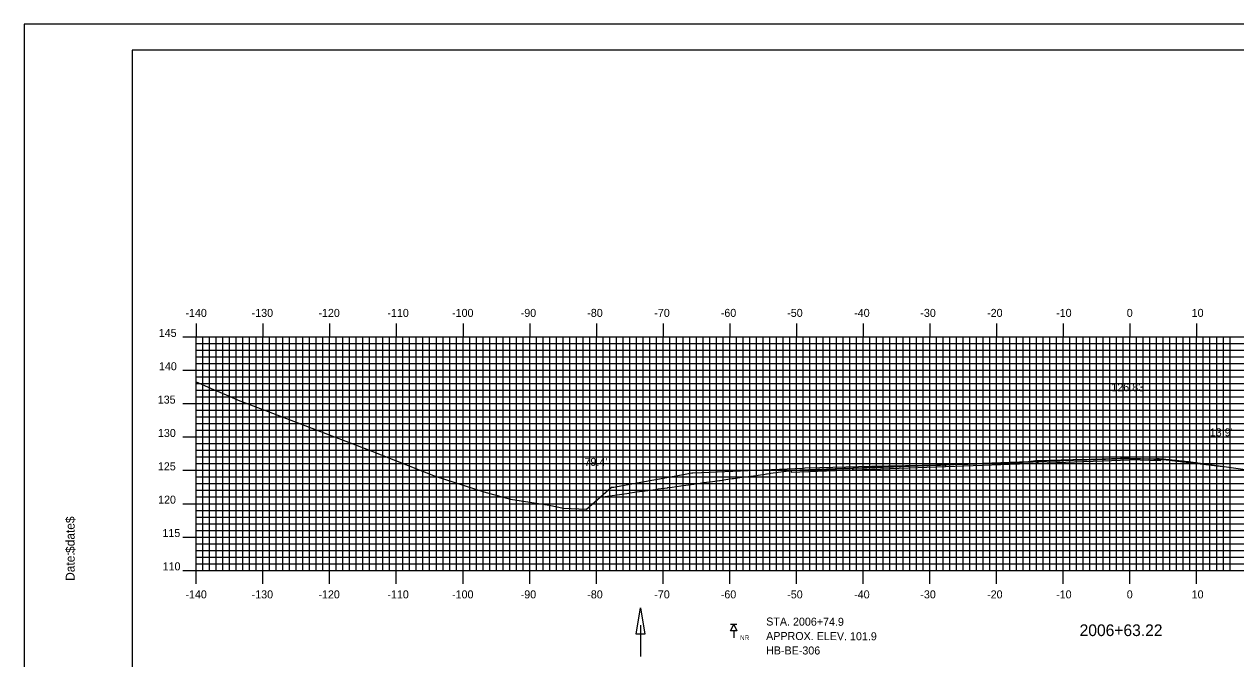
# Model space of a CAD drawing. Extents: x 852320 to 852663, y 366605 to 366825.
# Drawn here: x 852319.7 to 852501.3, y 366729.8 to 366824.9 of the extents above; entities that cross this region are included whole.
import ezdxf

# ---------------------------------------------------------------- set-up
doc = ezdxf.new("R2010")
doc.units = 0
for name, color, linetype in [('BORDER', 7, 'Continuous'), ('BORING - NO REFUSAL', 7, 'Continuous'), ('D_Drainage_Ditch_Line', 7, 'Continuous'), ('D_Roadway_Centerline', 7, 'Continuous'), ('D_Roadway_Centerline_Text', 7, 'Continuous'), ('D_Roadway_Edge_Shoulder', 7, 'Continuous'), ('D_Roadway_Edge_TW', 7, 'Continuous'), ('D_Roadway_SlopeLines', 7, 'Continuous'), ('D_Text_Standard', 7, 'Continuous'), ('H_V ANNOTATION', 7, 'Continuous'), ('MAJOR', 7, 'Continuous'), ('MINOR', 7, 'Continuous'), ('PLOT BOUNDARY', 7, 'Continuous'), ('S_Roadway_Centerline', 7, 'Continuous')]:
    doc.layers.add(name, color=color, linetype=linetype)

msp = doc.modelspace()

# ---------------------------------------------------------------- linework, layer by layer
at = {"layer": 'BORDER'}
msp.add_lwpolyline([(852335.88, 366611.06), (852655.88, 366611.06), (852655.88, 366821.06), (852335.88, 366821.06)], close=True, dxfattribs=at)
at = {"layer": 'BORING - NO REFUSAL'}
for p, q in [((852426.56, 366734.96), (852425.6, 366734.96)), ((852426.08, 366734), (852426.08, 366732.94))]:
    msp.add_line(p, q, dxfattribs=at)
msp.add_lwpolyline([(852426.08, 366734.96), (852426.56, 366734), (852425.6, 366734)], close=True, dxfattribs=at)
at = {"layer": 'D_Drainage_Ditch_Line'}
msp.add_line((852412.09, 366734.83), (852412.09, 366730.13), dxfattribs=at)
msp.add_lwpolyline([(852412.74, 366733.52), (852411.43, 366733.52), (852412.09, 366737.45)], close=True, dxfattribs=at)
at = {"layer": 'D_Roadway_Centerline'}
msp.add_lwpolyline([(852406.05, 366754.04), (852410.41, 366754.65), (852410.51, 366754.67), (852410.55, 366754.67), (852411.21, 366754.76), (852412.27, 366754.91), (852412.42, 366754.93), (852413.96, 366755.15), (852414.33, 366755.2), (852414.73, 366755.26), (852416.13, 366755.45), (852416.21, 366755.46), (852416.24, 366755.47), (852416.83, 366755.55), (852418.16, 366755.73), (852418.9, 366755.84), (852420.07, 366756), (852420.52, 366756.06), (852421.06, 366756.14), (852421.54, 366756.21), (852422, 366756.27), (852422.88, 366756.39), (852423.92, 366756.54), (852423.96, 366756.54), (852424.02, 366756.55), (852425.18, 366756.71), (852425.85, 366756.81), (852425.96, 366756.82), (852426.02, 366756.83), (852427.27, 366757.01), (852427.78, 366757.08), (852428.26, 366757.14), (852429.71, 366757.35), (852430.8, 366757.5), (852430.99, 366757.53), (852431.08, 366757.54), (852431.65, 366757.62), (852433.5, 366757.88), (852433.58, 366757.89), (852434.67, 366758.04), (852435.38, 366758.07), (852435.53, 366758.07), (852435.57, 366758.07), (852435.98, 366758.09), (852437.08, 366758.13), (852437.47, 366758.14), (852438.59, 366758.18), (852439.42, 366758.21), (852440.39, 366758.25), (852441, 366758.27), (852441.11, 366758.27), (852441.37, 366758.28), (852442.4, 366758.32), (852442.6, 366758.33), (852442.69, 366758.33), (852443.32, 366758.35), (852443.43, 366758.36), (852443.93, 366758.38), (852445.28, 366758.42), (852445.35, 366758.43), (852446.03, 366758.45), (852446.97, 366758.49), (852447.24, 366758.49), (852448.55, 366758.54), (852449.2, 366758.57), (852450.03, 366758.6), (852451.08, 366758.63), (852451.12, 366758.64), (852451.16, 366758.64), (852452.36, 366758.68), (852453.13, 366758.71), (852453.71, 366758.73), (852455.1, 366758.78), (852455.29, 366758.79), (852456.15, 366758.82), (852456.25, 366758.82), (852457.08, 366758.85), (852457.8, 366758.88), (852459.06, 366758.92), (852460.63, 366758.98), (852461.04, 366758.99), (852461.08, 366759), (852461.24, 366759), (852461.39, 366759.01), (852461.44, 366759.01), (852462.49, 366759.05), (852463.02, 366759.07), (852463.9, 366759.1), (852465.01, 366759.14), (852465.78, 366759.17), (852466.35, 366759.19), (852466.59, 366759.2), (852467, 366759.21), (852468.54, 366759.27), (852468.99, 366759.28), (852469.32, 366759.29), (852470.98, 366759.35), (852471.01, 366759.36), (852471.48, 366759.37), (852471.65, 366759.38), (852472.85, 366759.42), (852472.98, 366759.43), (852474.56, 366759.48), (852474.98, 366759.5), (852475.44, 366759.52), (852476.63, 366759.56), (852476.76, 366759.57), (852476.99, 366759.57), (852478.06, 366759.61), (852478.99, 366759.65), (852479.94, 366759.68), (852480.57, 366759.7), (852480.72, 366759.71), (852481.01, 366759.72), (852481.58, 366759.74), (852481.8, 366759.75), (852482.1, 366759.76), (852483.02, 366759.79), (852483.33, 366759.8), (852485.04, 366759.87), (852485.09, 366759.87), (852485.48, 366759.88), (852487, 366759.83), (852487.04, 366759.82), (852487.06, 366759.82), (852488.3, 366759.78), (852489.08, 366759.75), (852489.38, 366759.73), (852490.08, 366759.71)], dxfattribs=at)
at = {"layer": 'D_Roadway_Edge_Shoulder'}
for points in [[(852485.48, 366759.88), (852490.08, 366759.71), (852490.08, 366759.46), (852485.48, 366759.63)], [(852443.93, 366758.38), (852434.67, 366758.04), (852434.67, 366757.79), (852443.93, 366758.13)]]:
    msp.add_lwpolyline(points, close=True, dxfattribs=at)
at = {"layer": 'D_Roadway_Edge_TW'}
for points in [[(852471.65, 366759.38), (852457.8, 366758.88), (852457.8, 366758.63), (852471.65, 366759.13)], [(852485.48, 366759.88), (852471.65, 366759.38), (852471.65, 366759.13), (852485.48, 366759.63)], [(852457.8, 366758.88), (852443.93, 366758.38), (852443.93, 366758.13), (852457.8, 366758.63)]]:
    msp.add_lwpolyline(points, close=True, dxfattribs=at)
msp.add_lwpolyline([(852457.8, 366758.63), (852457.8, 366758.88)], dxfattribs=at)
at = {"layer": 'D_Roadway_SlopeLines'}
msp.add_line((852490.08, 366759.71), (852499.39, 366758.65), dxfattribs=at)
at = {"layer": 'MAJOR'}
for p, q in [((852345.48, 366780.06), (852345.48, 366778.06)), ((852355.48, 366780.06), (852355.48, 366778.06)), ((852365.48, 366780.06), (852365.48, 366778.06)), ((852375.48, 366780.06), (852375.48, 366778.06)), ((852385.48, 366780.06), (852385.48, 366778.06)), ((852395.48, 366780.06), (852395.48, 366778.06)), ((852405.48, 366780.06), (852405.48, 366778.06)), ((852415.48, 366780.06), (852415.48, 366778.06)), ((852425.48, 366780.06), (852425.48, 366778.06)), ((852435.48, 366780.06), (852435.48, 366778.06)), ((852445.48, 366780.06), (852445.48, 366778.06)), ((852455.48, 366780.06), (852455.48, 366778.06)), ((852465.48, 366780.06), (852465.48, 366778.06)), ((852475.48, 366780.06), (852475.48, 366778.06)), ((852485.48, 366780.06), (852485.48, 366778.06)), ((852495.48, 366780.06), (852495.48, 366778.06)), ((852343.47, 366778.06), (852345.48, 366778.06)), ((852345.48, 366778.06), (852625.48, 366778.06)), ((852345.48, 366743.06), (852345.48, 366778.06)), ((852345.48, 366743.06), (852345.48, 366778.06)), ((852345.48, 366778.06), (852625.48, 366778.06)), ((852355.48, 366743.06), (852355.48, 366778.06)), ((852365.48, 366743.06), (852365.48, 366778.06)), ((852375.48, 366743.06), (852375.48, 366778.06)), ((852385.48, 366743.06), (852385.48, 366778.06)), ((852395.48, 366743.06), (852395.48, 366778.06)), ((852405.48, 366743.06), (852405.48, 366778.06)), ((852415.48, 366743.06), (852415.48, 366778.06)), ((852425.48, 366743.06), (852425.48, 366778.06)), ((852435.48, 366743.06), (852435.48, 366778.06)), ((852445.48, 366743.06), (852445.48, 366778.06)), ((852455.48, 366743.06), (852455.48, 366778.06)), ((852465.48, 366743.06), (852465.48, 366778.06)), ((852475.48, 366743.06), (852475.48, 366778.06)), ((852485.48, 366743.06), (852485.48, 366778.06)), ((852495.48, 366743.06), (852495.48, 366778.06)), ((852343.47, 366773.06), (852345.48, 366773.06)), ((852345.48, 366773.06), (852625.48, 366773.06)), ((852343.47, 366768.06), (852345.48, 366768.06)), ((852345.48, 366768.06), (852625.48, 366768.06)), ((852343.47, 366763.06), (852345.48, 366763.06)), ((852345.48, 366763.06), (852625.48, 366763.06)), ((852343.47, 366758.06), (852345.48, 366758.06)), ((852345.48, 366758.06), (852625.48, 366758.06)), ((852343.47, 366753.06), (852345.48, 366753.06)), ((852345.48, 366753.06), (852625.48, 366753.06)), ((852343.47, 366748.06), (852345.48, 366748.06)), ((852345.48, 366748.06), (852625.48, 366748.06)), ((852343.47, 366743.06), (852345.48, 366743.06)), ((852345.48, 366743.06), (852625.48, 366743.06)), ((852345.48, 366743.06), (852625.48, 366743.06)), ((852345.48, 366741.05), (852345.48, 366743.06)), ((852355.48, 366741.05), (852355.48, 366743.06)), ((852365.48, 366741.05), (852365.48, 366743.06)), ((852375.48, 366741.05), (852375.48, 366743.06)), ((852385.48, 366741.05), (852385.48, 366743.06)), ((852395.48, 366741.05), (852395.48, 366743.06)), ((852405.48, 366741.05), (852405.48, 366743.06)), ((852415.48, 366741.05), (852415.48, 366743.06)), ((852425.48, 366741.05), (852425.48, 366743.06)), ((852435.48, 366741.05), (852435.48, 366743.06)), ((852445.48, 366741.05), (852445.48, 366743.06)), ((852455.48, 366741.05), (852455.48, 366743.06)), ((852465.48, 366741.05), (852465.48, 366743.06)), ((852475.48, 366741.05), (852475.48, 366743.06)), ((852485.48, 366741.05), (852485.48, 366743.06)), ((852495.48, 366741.05), (852495.48, 366743.06))]:
    msp.add_line(p, q, dxfattribs=at)
at = {"layer": 'MINOR'}
for p, q in [((852345.48, 366743.06), (852345.48, 366778.06)), ((852345.48, 366777.06), (852625.48, 366777.06)), ((852345.48, 366777.06), (852347.48, 366777.06)), ((852346.48, 366743.06), (852346.48, 366778.06)), ((852347.48, 366743.06), (852347.48, 366778.06)), ((852348.48, 366743.06), (852348.48, 366778.06)), ((852349.48, 366743.06), (852349.48, 366778.06)), ((852350.48, 366743.06), (852350.48, 366778.06)), ((852351.48, 366743.06), (852351.48, 366778.06)), ((852352.48, 366743.06), (852352.48, 366778.06)), ((852353.48, 366743.06), (852353.48, 366778.06)), ((852354.48, 366743.06), (852354.48, 366778.06)), ((852356.48, 366743.06), (852356.48, 366778.06)), ((852357.48, 366743.06), (852357.48, 366778.06)), ((852358.48, 366743.06), (852358.48, 366778.06)), ((852359.48, 366743.06), (852359.48, 366778.06)), ((852360.48, 366743.06), (852360.48, 366778.06)), ((852361.48, 366743.06), (852361.48, 366778.06)), ((852362.48, 366743.06), (852362.48, 366778.06)), ((852363.48, 366743.06), (852363.48, 366778.06)), ((852364.48, 366743.06), (852364.48, 366778.06)), ((852366.48, 366743.06), (852366.48, 366778.06)), ((852367.48, 366743.06), (852367.48, 366778.06)), ((852368.48, 366743.06), (852368.48, 366778.06)), ((852369.48, 366743.06), (852369.48, 366778.06)), ((852370.48, 366743.06), (852370.48, 366778.06)), ((852371.48, 366743.06), (852371.48, 366778.06)), ((852372.48, 366743.06), (852372.48, 366778.06)), ((852373.48, 366743.06), (852373.48, 366778.06)), ((852374.48, 366743.06), (852374.48, 366778.06)), ((852376.48, 366743.06), (852376.48, 366778.06)), ((852377.48, 366743.06), (852377.48, 366778.06)), ((852378.48, 366743.06), (852378.48, 366778.06)), ((852379.48, 366743.06), (852379.48, 366778.06)), ((852380.48, 366743.06), (852380.48, 366778.06)), ((852381.48, 366743.06), (852381.48, 366778.06)), ((852382.48, 366743.06), (852382.48, 366778.06)), ((852383.48, 366743.06), (852383.48, 366778.06)), ((852384.48, 366743.06), (852384.48, 366778.06)), ((852386.48, 366743.06), (852386.48, 366778.06)), ((852387.48, 366743.06), (852387.48, 366778.06)), ((852388.48, 366743.06), (852388.48, 366778.06)), ((852389.48, 366743.06), (852389.48, 366778.06)), ((852390.48, 366743.06), (852390.48, 366778.06)), ((852391.48, 366743.06), (852391.48, 366778.06)), ((852392.48, 366743.06), (852392.48, 366778.06)), ((852393.48, 366743.06), (852393.48, 366778.06)), ((852394.48, 366743.06), (852394.48, 366778.06)), ((852396.48, 366743.06), (852396.48, 366778.06)), ((852397.48, 366743.06), (852397.48, 366778.06)), ((852398.48, 366743.06), (852398.48, 366778.06)), ((852399.48, 366743.06), (852399.48, 366778.06)), ((852400.48, 366743.06), (852400.48, 366778.06)), ((852401.48, 366743.06), (852401.48, 366778.06)), ((852402.48, 366743.06), (852402.48, 366778.06)), ((852403.48, 366743.06), (852403.48, 366778.06)), ((852404.48, 366743.06), (852404.48, 366778.06)), ((852406.48, 366743.06), (852406.48, 366778.06)), ((852407.48, 366743.06), (852407.48, 366778.06)), ((852408.48, 366743.06), (852408.48, 366778.06)), ((852409.48, 366743.06), (852409.48, 366778.06)), ((852410.48, 366743.06), (852410.48, 366778.06)), ((852411.48, 366743.06), (852411.48, 366778.06)), ((852412.48, 366743.06), (852412.48, 366778.06)), ((852413.48, 366743.06), (852413.48, 366778.06)), ((852414.48, 366743.06), (852414.48, 366778.06)), ((852416.48, 366743.06), (852416.48, 366778.06)), ((852417.48, 366743.06), (852417.48, 366778.06)), ((852418.48, 366743.06), (852418.48, 366778.06)), ((852419.48, 366743.06), (852419.48, 366778.06)), ((852420.48, 366743.06), (852420.48, 366778.06)), ((852421.48, 366743.06), (852421.48, 366778.06)), ((852422.48, 366743.06), (852422.48, 366778.06)), ((852423.48, 366743.06), (852423.48, 366778.06)), ((852424.48, 366743.06), (852424.48, 366778.06)), ((852426.48, 366743.06), (852426.48, 366778.06)), ((852427.48, 366743.06), (852427.48, 366778.06)), ((852428.48, 366743.06), (852428.48, 366778.06)), ((852429.48, 366743.06), (852429.48, 366778.06)), ((852430.48, 366743.06), (852430.48, 366778.06)), ((852431.48, 366743.06), (852431.48, 366778.06)), ((852432.48, 366743.06), (852432.48, 366778.06)), ((852433.48, 366743.06), (852433.48, 366778.06)), ((852434.48, 366743.06), (852434.48, 366778.06)), ((852436.48, 366743.06), (852436.48, 366778.06)), ((852437.48, 366743.06), (852437.48, 366778.06)), ((852438.48, 366743.06), (852438.48, 366778.06)), ((852439.48, 366743.06), (852439.48, 366778.06)), ((852440.48, 366743.06), (852440.48, 366778.06)), ((852441.48, 366743.06), (852441.48, 366778.06)), ((852442.48, 366743.06), (852442.48, 366778.06)), ((852443.48, 366743.06), (852443.48, 366778.06)), ((852444.48, 366743.06), (852444.48, 366778.06)), ((852446.48, 366743.06), (852446.48, 366778.06)), ((852447.48, 366743.06), (852447.48, 366778.06)), ((852448.48, 366743.06), (852448.48, 366778.06)), ((852449.48, 366743.06), (852449.48, 366778.06)), ((852450.48, 366743.06), (852450.48, 366778.06)), ((852451.48, 366743.06), (852451.48, 366778.06)), ((852452.48, 366743.06), (852452.48, 366778.06)), ((852453.48, 366743.06), (852453.48, 366778.06)), ((852454.48, 366743.06), (852454.48, 366778.06)), ((852456.48, 366743.06), (852456.48, 366778.06)), ((852457.48, 366743.06), (852457.48, 366778.06)), ((852458.48, 366743.06), (852458.48, 366778.06)), ((852459.48, 366743.06), (852459.48, 366778.06)), ((852460.48, 366743.06), (852460.48, 366778.06)), ((852461.48, 366743.06), (852461.48, 366778.06)), ((852462.48, 366743.06), (852462.48, 366778.06)), ((852463.48, 366743.06), (852463.48, 366778.06)), ((852464.48, 366743.06), (852464.48, 366778.06)), ((852466.48, 366743.06), (852466.48, 366778.06)), ((852467.48, 366743.06), (852467.48, 366778.06)), ((852468.48, 366743.06), (852468.48, 366778.06)), ((852469.48, 366743.06), (852469.48, 366778.06)), ((852470.48, 366743.06), (852470.48, 366778.06)), ((852471.48, 366743.06), (852471.48, 366778.06)), ((852472.48, 366743.06), (852472.48, 366778.06)), ((852473.48, 366743.06), (852473.48, 366778.06)), ((852474.48, 366743.06), (852474.48, 366778.06)), ((852476.48, 366743.06), (852476.48, 366778.06)), ((852477.48, 366743.06), (852477.48, 366778.06)), ((852478.48, 366743.06), (852478.48, 366778.06)), ((852479.48, 366743.06), (852479.48, 366778.06)), ((852480.48, 366743.06), (852480.48, 366778.06)), ((852481.48, 366743.06), (852481.48, 366778.06)), ((852482.48, 366743.06), (852482.48, 366778.06)), ((852483.48, 366743.06), (852483.48, 366778.06)), ((852484.48, 366743.06), (852484.48, 366778.06)), ((852486.48, 366743.06), (852486.48, 366778.06)), ((852487.48, 366743.06), (852487.48, 366778.06)), ((852488.48, 366743.06), (852488.48, 366778.06)), ((852489.48, 366743.06), (852489.48, 366778.06)), ((852490.48, 366743.06), (852490.48, 366778.06)), ((852491.48, 366743.06), (852491.48, 366778.06)), ((852492.48, 366743.06), (852492.48, 366778.06)), ((852493.48, 366743.06), (852493.48, 366778.06)), ((852494.48, 366743.06), (852494.48, 366778.06)), ((852496.48, 366743.06), (852496.48, 366778.06)), ((852497.48, 366743.06), (852497.48, 366778.06)), ((852498.48, 366743.06), (852498.48, 366778.06)), ((852499.48, 366743.06), (852499.48, 366778.06)), ((852500.48, 366743.06), (852500.48, 366778.06)), ((852345.48, 366776.06), (852625.48, 366776.06)), ((852345.48, 366776.06), (852347.48, 366776.06)), ((852345.48, 366775.06), (852625.48, 366775.06)), ((852345.48, 366775.06), (852347.48, 366775.06)), ((852345.48, 366774.06), (852625.48, 366774.06)), ((852345.48, 366774.06), (852347.48, 366774.06)), ((852345.48, 366772.06), (852625.48, 366772.06)), ((852345.48, 366772.06), (852347.48, 366772.06)), ((852345.48, 366771.06), (852625.48, 366771.06)), ((852345.48, 366771.06), (852347.48, 366771.06)), ((852345.48, 366770.06), (852625.48, 366770.06)), ((852345.48, 366770.06), (852347.48, 366770.06)), ((852345.48, 366769.06), (852625.48, 366769.06)), ((852345.48, 366769.06), (852347.48, 366769.06)), ((852345.48, 366767.06), (852625.48, 366767.06)), ((852345.48, 366767.06), (852347.48, 366767.06)), ((852345.48, 366766.06), (852625.48, 366766.06)), ((852345.48, 366766.06), (852347.48, 366766.06)), ((852345.48, 366765.06), (852625.48, 366765.06)), ((852345.48, 366765.06), (852347.48, 366765.06)), ((852345.48, 366764.06), (852625.48, 366764.06)), ((852345.48, 366764.06), (852347.48, 366764.06)), ((852345.48, 366762.06), (852625.48, 366762.06)), ((852345.48, 366762.06), (852347.48, 366762.06)), ((852345.48, 366761.06), (852625.48, 366761.06)), ((852345.48, 366761.06), (852347.48, 366761.06)), ((852345.48, 366760.06), (852625.48, 366760.06)), ((852345.48, 366760.06), (852347.48, 366760.06)), ((852345.48, 366759.06), (852625.48, 366759.06)), ((852345.48, 366759.06), (852347.48, 366759.06)), ((852345.48, 366757.06), (852625.48, 366757.06)), ((852345.48, 366757.06), (852347.48, 366757.06)), ((852345.48, 366756.06), (852625.48, 366756.06)), ((852345.48, 366756.06), (852347.48, 366756.06)), ((852345.48, 366755.06), (852625.48, 366755.06)), ((852345.48, 366755.06), (852347.48, 366755.06)), ((852345.48, 366754.06), (852625.48, 366754.06)), ((852345.48, 366754.06), (852347.48, 366754.06)), ((852345.48, 366752.06), (852625.48, 366752.06)), ((852345.48, 366752.06), (852347.48, 366752.06)), ((852345.48, 366751.06), (852625.48, 366751.06)), ((852345.48, 366751.06), (852347.48, 366751.06)), ((852345.48, 366750.06), (852625.48, 366750.06)), ((852345.48, 366750.06), (852347.48, 366750.06)), ((852345.48, 366749.06), (852625.48, 366749.06)), ((852345.48, 366749.06), (852347.48, 366749.06)), ((852345.48, 366747.06), (852625.48, 366747.06)), ((852345.48, 366747.06), (852347.48, 366747.06)), ((852345.48, 366746.06), (852625.48, 366746.06)), ((852345.48, 366746.06), (852347.48, 366746.06)), ((852345.48, 366745.06), (852625.48, 366745.06)), ((852345.48, 366745.06), (852347.48, 366745.06)), ((852345.48, 366744.06), (852625.48, 366744.06)), ((852345.48, 366744.06), (852347.48, 366744.06))]:
    msp.add_line(p, q, dxfattribs=at)
at = {"layer": 'PLOT BOUNDARY'}
msp.add_lwpolyline([(852319.69, 366604.94), (852659.69, 366604.94), (852659.69, 366824.94), (852319.69, 366824.94)], close=True, dxfattribs=at)
at = {"layer": 'S_Roadway_Centerline'}
msp.add_lwpolyline([(852345.48, 366771.35), (852348.08, 366770.2), (852350.32, 366769.22), (852351.78, 366768.58), (852357.3, 366766.47), (852371.33, 366761.11), (852381.31, 366757.16), (852388.61, 366754.84), (852392.61, 366753.71), (852398.38, 366752.82), (852400.53, 366752.39), (852403.98, 366752.22), (852407.74, 366755.54), (852408.07, 366755.55), (852409.39, 366755.76), (852418.8, 366757.5), (852419.79, 366757.69), (852419.81, 366757.69), (852419.95, 366757.69), (852421.26, 366757.75), (852436.41, 366758.39), (852436.74, 366758.41), (852436.79, 366758.41), (852438.96, 366758.46), (852446.73, 366758.66), (852456.89, 366758.88), (852465.6, 366759.18), (852469.05, 366759.31), (852470.35, 366759.36), (852471.33, 366759.51), (852471.66, 366759.51), (852476.9, 366759.67), (852482.35, 366759.78), (852489.51, 366759.81), (852489.85, 366759.85), (852494.25, 366759.39), (852504.54, 366757.92)], dxfattribs=at)

# ---------------------------------------------------------------- texts
at = {"layer": 'BORDER'}
for s, p in [('$date$', (852327.25, 366745.67)), ('Date:', (852327.25, 366741.49))]:
    msp.add_text(s, height=1.339, rotation=90, dxfattribs=at).set_placement(p)
at = {"layer": 'BORING - NO REFUSAL'}
for s, p in [('STA. 2006+74.9', (852430.94, 366734.79)), ('APPROX. ELEV. 101.9', (852430.93, 366732.63)), ('HB-BE-306', (852430.92, 366730.47))]:
    msp.add_text(s, height=1.2, rotation=359.8142, dxfattribs=at).set_placement(p)
msp.add_text('NR', height=0.7, dxfattribs=at).set_placement((852427.01, 366732.62))
at = {"layer": 'D_Roadway_Centerline_Text'}
msp.add_text('126.83', height=1.2, dxfattribs=at).set_placement((852482.69, 366769.91))
at = {"layer": 'D_Text_Standard'}
for s, p in [("13.9'", (852497.45, 366763.16)), ("79.4'", (852403.69, 366758.72))]:
    msp.add_text(s, height=1.2, dxfattribs=at).set_placement(p)
at = {"layer": 'H_V ANNOTATION'}
for s, height, p in [('-140', 1.2, (852343.86, 366781.06)), ('-130', 1.2, (852353.79, 366781.06)), ('-120', 1.2, (852363.8, 366781.06)), ('-110', 1.2, (852374.14, 366781.06)), ('-100', 1.2, (852383.84, 366781.06)), ('-90', 1.2, (852394.13, 366781.06)), ('-80', 1.2, (852404.11, 366781.06)), ('-70', 1.2, (852414.16, 366781.06)), ('-60', 1.2, (852424.13, 366781.06)), ('-50', 1.2, (852434.09, 366781.06)), ('-40', 1.2, (852444.13, 366781.06)), ('-30', 1.2, (852454.05, 366781.06)), ('-20', 1.2, (852464.06, 366781.06)), ('-10', 1.2, (852474.41, 366781.06)), ('0', 1.2, (852485, 366781.06)), ('10', 1.2, (852494.73, 366781.06)), ('145', 1.2, (852339.86, 366778.06)), ('140', 1.2, (852339.89, 366773.06)), ('135', 1.2, (852339.71, 366768.06)), ('130', 1.2, (852339.74, 366763.06)), ('125', 1.2, (852339.73, 366758.06)), ('120', 1.2, (852339.76, 366753.06)), ('115', 1.2, (852340.41, 366748.06)), ('110', 1.2, (852340.44, 366743.06)), ('-140', 1.2, (852343.86, 366738.86)), ('-130', 1.2, (852353.79, 366738.86)), ('-120', 1.2, (852363.8, 366738.86)), ('-110', 1.2, (852374.14, 366738.86)), ('-100', 1.2, (852383.84, 366738.86)), ('-90', 1.2, (852394.13, 366738.86)), ('-80', 1.2, (852404.11, 366738.86)), ('-70', 1.2, (852414.16, 366738.86)), ('-60', 1.2, (852424.13, 366738.86)), ('-50', 1.2, (852434.09, 366738.86)), ('-40', 1.2, (852444.13, 366738.86)), ('-30', 1.2, (852454.05, 366738.86)), ('-20', 1.2, (852464.06, 366738.86)), ('-10', 1.2, (852474.41, 366738.86)), ('0', 1.2, (852485, 366738.86)), ('10', 1.2, (852494.73, 366738.86)), ('2006+63.22', 1.75, (852477.93, 366733.21))]:
    msp.add_text(s, height=height, dxfattribs=at).set_placement(p)
at = {"layer": 'MAJOR'}
msp.add_text('-', height=0.012, dxfattribs=at).set_placement((852345.47, 366743.06))

doc.saveas('drawing.dxf')
